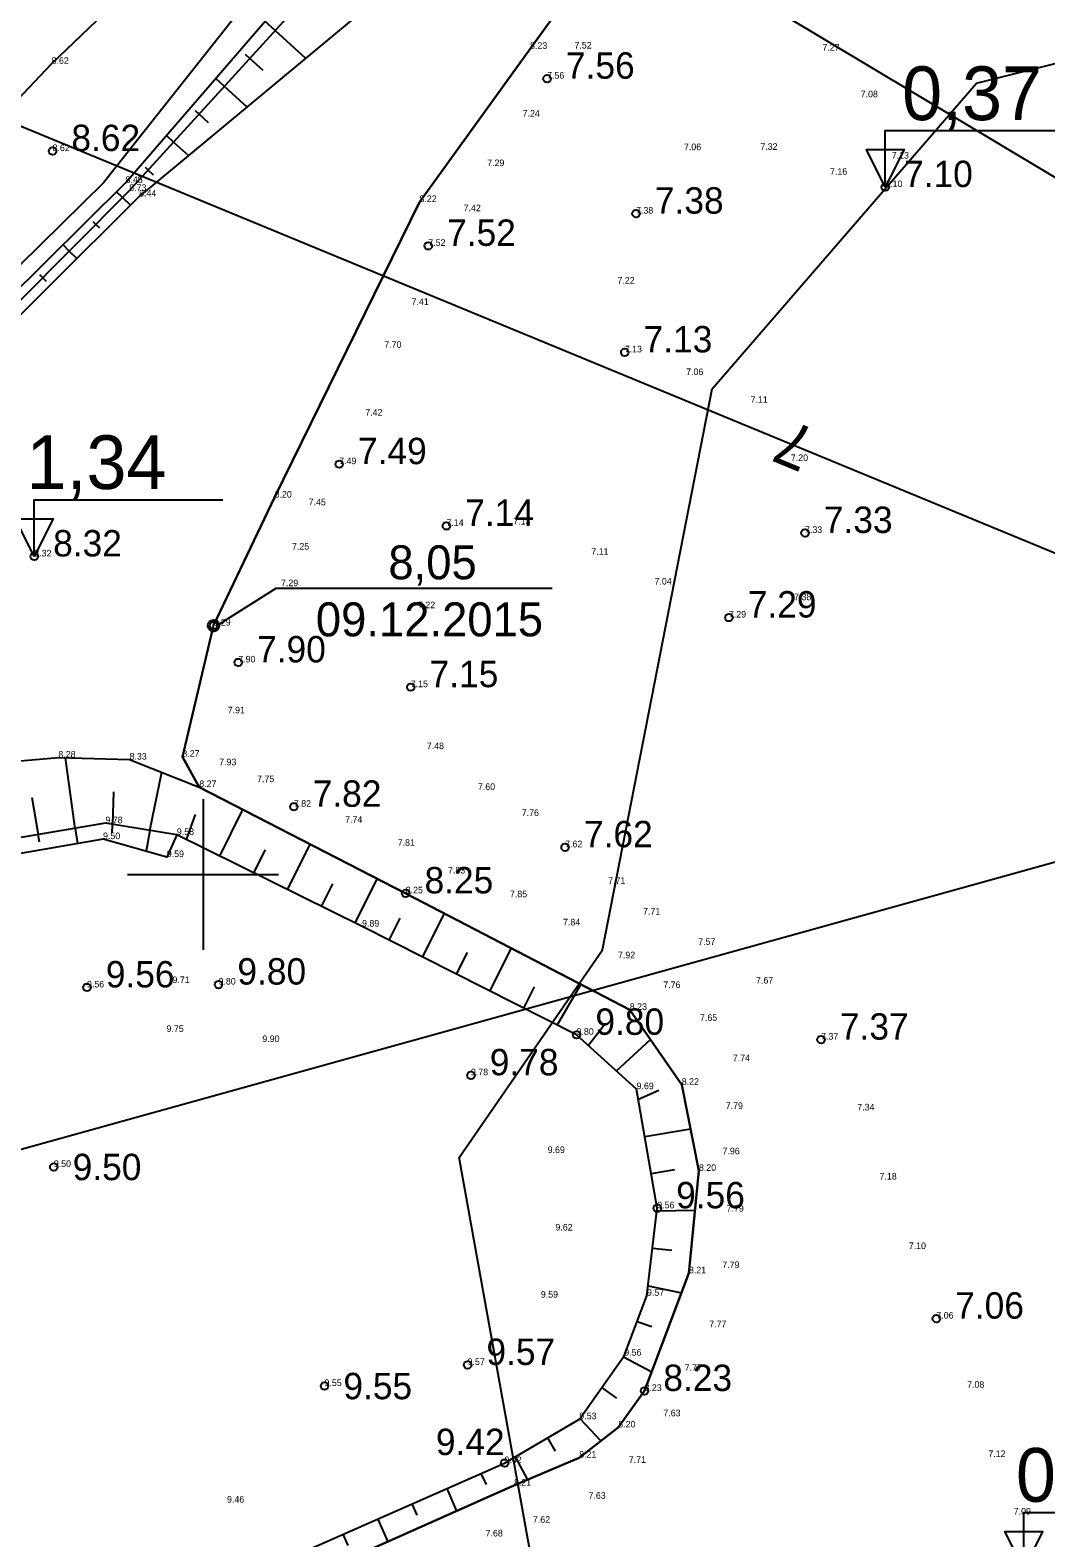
# Model space of a CAD drawing. Extents: x 433497 to 434382, y 6534486 to 6534993.
# Drawn here: x 433890.8 to 433944.7, y 6534764.8 to 6534844.8 of the extents above; entities that cross this region are included whole.
import ezdxf

# ---------------------------------------------------------------- set-up
doc = ezdxf.new("R2010")
doc.units = 0
for name, color, linetype in [('jääkpaksus', 7, 'Continuous'), ('KORGUS', 7, 'Continuous'), ('KORGUS-EH2000', 7, 'Continuous'), ('l__x00e4__bil__x00f5__iked', 7, 'Continuous'), ('Lamami horisontaal', 7, 'Continuous'), ('MOOTKORG-EH2000', 7, 'Continuous'), ('PIIR', 7, 'Continuous'), ('RELJEEF', 7, 'Continuous'), ('TEE', 7, 'Continuous'), ('VEEKOGU', 7, 'Continuous'), ('VORK', 7, 'Continuous')]:
    doc.layers.add(name, color=color, linetype=linetype)

msp = doc.modelspace()

# ---------------------------------------------------------------- linework, layer by layer
at = {"layer": 'jääkpaksus'}
for points in [[(433936.167, 6534836.451), (433936.167, 6534839.451), (433946.167, 6534839.451)], [(433891.052, 6534816.863), (433891.052, 6534819.863), (433901.052, 6534819.863)], [(433943.508, 6534763.157), (433943.508, 6534766.157), (433953.508, 6534766.157)]]:
    msp.add_lwpolyline(points, dxfattribs=at)
for points in [[(433936.167, 6534836.451), (433935.167, 6534838.451), (433937.167, 6534838.451)], [(433891.052, 6534816.863), (433890.052, 6534818.863), (433892.052, 6534818.863)], [(433943.508, 6534763.157), (433942.508, 6534765.157), (433944.508, 6534765.157)]]:
    msp.add_lwpolyline(points, close=True, dxfattribs=at)
at = {"layer": 'KORGUS'}
for centre in [(433892.086, 6534784.487), (433906.439, 6534772.869)]:
    msp.add_circle(centre, 0.2, dxfattribs=at)
at = {"layer": 'KORGUS-EH2000'}
for centre in [(433918.239, 6534842.2), (433892.019, 6534838.361), (433936.167, 6534836.451), (433922.956, 6534835.043), (433911.94, 6534833.335), (433922.358, 6534827.686), (433907.215, 6534821.758), (433912.903, 6534818.485), (433931.914, 6534818.11), (433891.052, 6534816.863), (433927.88, 6534813.625), (433901.866, 6534811.243), (433911.012, 6534809.931), (433904.812, 6534803.588), (433919.195, 6534801.44), (433910.743, 6534798.994), (433893.844, 6534794.007), (433900.819, 6534794.16), (433919.801, 6534791.494), (433932.765, 6534791.239), (433914.2, 6534789.346), (433892.086, 6534784.487), (433924.081, 6534782.294), (433938.877, 6534776.443), (433914.023, 6534773.986), (433923.404, 6534772.606), (433915.987, 6534768.78)]:
    msp.add_circle(centre, 0.2, dxfattribs=at)
at = {"layer": 'l__x00e4__bil__x00f5__iked'}
for points in [[(433837.129, 6534901.88), (433863.279, 6534885.992), (433986.579, 6534812.177), (434090.185, 6534779.904), (434120.969, 6534768.153)], [(433620.07, 6534691.039), (433627.105, 6534692.187), (433736.834, 6534712.709), (433742.792, 6534710.723), (433822.234, 6534766.498), (433986.579, 6534812.177), (434120.472, 6534848.091), (434132.163, 6534850.175)]]:
    msp.add_lwpolyline(points, dxfattribs=at)
at = {"layer": 'Lamami horisontaal'}
msp.add_lwpolyline([(433937.053, 6534740.112), (433960.879, 6534790.248), (433963.322, 6534798.12), (433962.586, 6534804.768), (433958.672, 6534810.191), (433951.578, 6534814.39), (433862.504, 6534851.176), (433857.642, 6534852.614), (433852.859, 6534852.881), (433848.155, 6534851.977), (433843.529, 6534849.902), (433823.019, 6534838.004), (433819.889, 6534836.728), (433817.507, 6534836.964), (433815.874, 6534838.714), (433814.99, 6534841.977), (433812.452, 6534861.972), (433812.459, 6534863.884), (433813.004, 6534865.497), (433813.579, 6534866.195)], dxfattribs=at)
at = {"layer": 'PIIR'}
msp.add_lwpolyline([(433924.608, 6534718.343), (433917.99, 6534737.895), (433917.54, 6534763.005), (433913.58, 6534784.995), (433921.17, 6534796.005), (433926.99, 6534825.75), (433941, 6534841.965), (433961.01, 6534846.975), (433983.99, 6534835.44), (434035.235, 6534886.132)], dxfattribs=at)
at = {"layer": 'RELJEEF'}
for p, q in [((433903.823, 6534844.753), (433903.282, 6534845.245)), ((433903.823, 6534844.753), (433905.431, 6534843.29)), ((433902.227, 6534843.501), (433902.478, 6534843.273)), ((433903.178, 6534842.636), (433902.478, 6534843.273)), ((433901.132, 6534841.794), (433900.669, 6534842.215)), ((433901.132, 6534841.794), (433902.325, 6534840.708)), ((433899.574, 6534840.507), (433899.786, 6534840.314)), ((433900.279, 6534839.865), (433899.786, 6534840.314)), ((433898.44, 6534838.835), (433898.055, 6534839.185)), ((433898.44, 6534838.835), (433899.22, 6534838.125)), ((433896.922, 6534837.514), (433897.094, 6534837.355)), ((433897.379, 6534837.093), (433897.094, 6534837.355)), ((433895.732, 6534835.892), (433895.412, 6534836.2)), ((433895.732, 6534835.892), (433896.145, 6534835.493)), ((433894.158, 6534834.636), (433894.321, 6534834.475)), ((433894.521, 6534834.275), (433894.321, 6534834.475)), ((433892.909, 6534833.058), (433892.575, 6534833.39)), ((433892.909, 6534833.058), (433893.304, 6534832.664)), ((433891.326, 6534831.812), (433891.498, 6534831.641)), ((433891.692, 6534831.447), (433891.498, 6534831.641)), ((433893.226, 6534802.444), (433892.711, 6534806.189)), ((433897.172, 6534802.33), (433897.805, 6534805.42)), ((433890.92, 6534804.08), (433891.254, 6534802.11)), ((433895.247, 6534804.383), (433895.198, 6534802.652)), ((433899.58, 6534803.175), (433899.096, 6534801.854)), ((433900.889, 6534800.966), (433902.114, 6534803.441)), ((433893.226, 6534802.444), (433893.337, 6534801.637)), ((433895.185, 6534802.196), (433895.198, 6534802.652)), ((433897.172, 6534802.33), (433896.991, 6534801.226)), ((433891.322, 6534801.705), (433891.254, 6534802.11)), ((433904.473, 6534799.191), (433905.67, 6534801.608)), ((433903.286, 6534801.302), (433902.681, 6534800.079)), ((433908.058, 6534797.416), (433909.233, 6534799.772)), ((433906.857, 6534799.498), (433906.265, 6534798.304)), ((433910.432, 6534797.684), (433909.845, 6534796.518)), ((433911.63, 6534795.617), (433912.796, 6534797.927)), ((433913.993, 6534795.86), (433913.416, 6534794.716)), ((433915.201, 6534793.815), (433916.345, 6534796.082)), ((433918.772, 6534792.013), (433920.021, 6534794.172)), ((433917.553, 6534794.037), (433916.987, 6534792.914)), ((433921.267, 6534792.007), (433920.43, 6534790.925)), ((433921.912, 6534789.583), (433923.714, 6534791.246)), ((433924.167, 6534788.544), (433923.079, 6534788.066)), ((433923.421, 6534786.096), (433925.843, 6534786.516)), ((433925.002, 6534784.327), (433923.763, 6534784.125)), ((433924.064, 6534782.153), (433926.086, 6534782.189)), ((433924.849, 6534780.048), (433923.831, 6534780.167)), ((433923.598, 6534778.181), (433925.369, 6534777.808)), ((433923.799, 6534776.007), (433923.013, 6534776.28)), ((433922.287, 6534774.419), (433923.785, 6534773.614)), ((433921.929, 6534772.224), (433921.133, 6534772.786)), ((433919.979, 6534771.152), (433921.09, 6534769.958)), ((433918.689, 6534769.417), (433918.27, 6534770.122)), ((433916.546, 6534769.109), (433917.198, 6534767.892)), ((433915.023, 6534767.646), (433914.75, 6534768.235)), ((433912.92, 6534767.428), (433913.445, 6534766.237)), ((433911.354, 6534766.023), (433911.09, 6534766.621)), ((433909.26, 6534765.814), (433909.789, 6534764.614)), ((433907.695, 6534764.405), (433907.43, 6534765.008))]:
    msp.add_line(p, q, dxfattribs=at)
for points in [[(433898.612, 6534802.094), (433898.076, 6534800.92), (433894.697, 6534801.873), (433884.69, 6534800.138), (433872.871, 6534792.485), (433865.209, 6534789.352), (433856.709, 6534790.266), (433854.429, 6534791.927), (433850.926, 6534796.169), (433848.567, 6534800.946), (433849.25, 6534803.887), (433849.579, 6534804.828), (433855.051, 6534806.361), (433863.497, 6534809.37), (433872.433, 6534814.392), (433881.08, 6534822.005), (433895.887, 6534836.671), (433906.99, 6534849.543)], [(433881.396, 6534821.499), (433896.085, 6534836.246), (433907.73, 6534849.047)], [(433909.717, 6534846.854), (433896.607, 6534835.953), (433881.875, 6534821.287)], [(433883.794, 6534805.462), (433892.328, 6534806.2), (433896.102, 6534806.091), (433899.798, 6534804.634), (433910.743, 6534798.994), (433922.624, 6534792.819), (433925.378, 6534788.845), (433926.29, 6534784.28), (433925.761, 6534778.847), (433923.404, 6534772.606), (433922.013, 6534770.671), (433919.938, 6534769.068), (433916.484, 6534767.586), (433905.134, 6534762.547)], [(433904.949, 6534763.914), (433915.987, 6534768.78), (433919.949, 6534771.11), (433922.329, 6534774.479), (433923.536, 6534777.656), (433924.081, 6534782.294), (433922.984, 6534788.612), (433919.801, 6534791.494), (433908.429, 6534797.232), (433898.612, 6534802.094), (433894.822, 6534802.714), (433884.378, 6534800.945)]]:
    msp.add_lwpolyline(points, dxfattribs=at)
at = {"layer": 'TEE'}
for points in [[(433861.438, 6534942.159), (433869.211, 6534941.983), (433884.56, 6534941.789), (433912.385, 6534941.438), (433914.504, 6534939.939), (433923.131, 6534931.509), (433926.468, 6534922.294), (433926.566, 6534912.494), (433924.107, 6534897.344), (433917.239, 6534875.453), (433907.496, 6534860.59), (433898.243, 6534848.994), (433898.296, 6534849.051), (433891.969, 6534842.99)], [(433946.971, 6534921.598), (433938.961, 6534918.789), (433932.862, 6534915.346), (433929.862, 6534910.084), (433927.993, 6534899.902), (433926.253, 6534890.427), (433921.703, 6534874.038), (433912.286, 6534858.358), (433907.932, 6534852.587), (433902.598, 6534846.653), (433894.713, 6534836.682), (433880.242, 6534822.442), (433871.952, 6534814.761), (433862.656, 6534809.713), (433848.041, 6534804.286)], [(433891.969, 6534842.99), (433881.334, 6534831.763), (433873.157, 6534823.586), (433858.917, 6534813.356), (433845.699, 6534809.155)]]:
    msp.add_lwpolyline(points, dxfattribs=at)
at = {"layer": 'VEEKOGU'}
for points in [[(433905.134, 6534762.547), (433916.484, 6534767.586), (433919.938, 6534769.068), (433922.013, 6534770.671), (433923.404, 6534772.606), (433925.761, 6534778.847), (433926.29, 6534784.28), (433925.378, 6534788.845), (433922.624, 6534792.819), (433910.743, 6534798.994), (433899.798, 6534804.634), (433898.901, 6534806.241), (433900.552, 6534813.199), (433903.795, 6534819.986), (433911.474, 6534835.66), (433917.335, 6534843.781), (433923.831, 6534852.766), (433925.728, 6534858.785), (433925.594, 6534862.047), (433930.79, 6534874.949), (433935.088, 6534889.742), (433939.821, 6534890.613), (433944.672, 6534889.281), (433947.125, 6534887.427)], [(433950.327, 6534886.209), (433947.125, 6534887.427), (433944.672, 6534889.281), (433939.821, 6534890.613), (433935.088, 6534889.742), (433930.79, 6534874.949), (433925.594, 6534862.047), (433925.728, 6534858.785), (433923.831, 6534852.766), (433917.335, 6534843.781), (433911.474, 6534835.66), (433903.795, 6534819.986), (433900.681, 6534813.47)], [(433918.513, 6534815.161), (433903.866, 6534815.161), (433900.752, 6534813.199)], [(433900.483, 6534812.907), (433898.901, 6534806.241), (433899.798, 6534804.634), (433910.743, 6534798.994), (433922.624, 6534792.819), (433925.378, 6534788.845), (433926.29, 6534784.28), (433925.761, 6534778.847), (433923.404, 6534772.606), (433922.013, 6534770.671), (433919.938, 6534769.068), (433916.484, 6534767.586), (433905.134, 6534762.547)]]:
    msp.add_lwpolyline(points, dxfattribs=at)
for radius in [0.3, 0.2]:
    msp.add_circle((433900.552, 6534813.199), radius, dxfattribs=at)
msp.add_arc((433900.552, 6534813.199), 0.3, 256.65167, 64.46035, dxfattribs=at)
at = {"layer": 'VORK'}
for p, q in [((433900, 6534804), (433900, 6534796)), ((433896, 6534800), (433904, 6534800))]:
    msp.add_line(p, q, dxfattribs=at)

# ---------------------------------------------------------------- texts
at = {"layer": 'jääkpaksus'}
for s, p in [('0,37', (433937.063, 6534840.002)), ('1,34', (433890.64, 6534820.438)), ('0,52', (433943.096, 6534766.732))]:
    msp.add_text(s, height=2.85, rotation=360, dxfattribs=at).set_placement(p)
at = {"layer": 'KORGUS-EH2000'}
for s, p in [('7.56', (433919.239, 6534842.2)), ('8.62', (433893.019, 6534838.361)), ('7.10', (433937.167, 6534836.451)), ('7.38', (433923.956, 6534835.043)), ('7.52', (433912.94, 6534833.335)), ('7.13', (433923.358, 6534827.686)), ('7.49', (433908.215, 6534821.758)), ('7.14', (433913.903, 6534818.485)), ('7.33', (433932.914, 6534818.11)), ('8.32', (433892.052, 6534816.863)), ('7.29', (433928.88, 6534813.625)), ('7.90', (433902.866, 6534811.243)), ('7.15', (433912.012, 6534809.931)), ('7.82', (433905.812, 6534803.588)), ('7.62', (433920.195, 6534801.44)), ('8.25', (433911.743, 6534798.994)), ('9.56', (433894.844, 6534794.007)), ('9.80', (433901.819, 6534794.16)), ('9.80', (433920.801, 6534791.494)), ('7.37', (433933.765, 6534791.239)), ('9.78', (433915.2, 6534789.346)), ('9.50', (433893.086, 6534783.787)), ('9.56', (433925.081, 6534782.294)), ('7.06', (433939.877, 6534776.443)), ('9.57', (433915.023, 6534773.986)), ('9.55', (433907.439, 6534772.169)), ('8.23', (433924.404, 6534772.606)), ('9.42', (433912.345, 6534769.207))]:
    msp.add_text(s, height=1.4, dxfattribs=at).set_placement(p)
at = {"layer": 'Lamami horisontaal'}
msp.add_text('7', height=2.4, rotation=157.56033, dxfattribs=at).set_placement((433932.62, 6534823.517))
at = {"layer": 'MOOTKORG-EH2000'}
for s, p in [('8.23', (433917.335, 6534843.781)), ('7.52', (433919.689, 6534843.8)), ('7.27', (433932.837, 6534843.689)), ('8.62', (433891.969, 6534842.99)), ('7.56', (433918.239, 6534842.2)), ('7.08', (433934.867, 6534841.214)), ('7.24', (433916.943, 6534840.186)), ('8.62', (433892.019, 6534838.361)), ('7.06', (433925.497, 6534838.41)), ('7.32', (433929.547, 6534838.427)), ('7.13', (433936.512, 6534837.959)), ('7.29', (433915.064, 6534837.563)), ('7.16', (433933.239, 6534837.103)), ('8.45', (433895.887, 6534836.671)), ('8.73', (433896.085, 6534836.246)), ('7.10', (433936.167, 6534836.451)), ('8.44', (433896.607, 6534835.953)), ('8.22', (433911.474, 6534835.66)), ('7.42', (433913.815, 6534835.174)), ('7.38', (433922.956, 6534835.043)), ('7.52', (433911.94, 6534833.335)), ('7.22', (433921.97, 6534831.332)), ('7.41', (433911.055, 6534830.202)), ('7.70', (433909.607, 6534827.93)), ('7.13', (433922.358, 6534827.686)), ('7.06', (433925.612, 6534826.483)), ('7.11', (433929.032, 6534825.012)), ('7.42', (433908.602, 6534824.328)), ('7.20', (433931.165, 6534821.923)), ('7.49', (433907.215, 6534821.758)), ('8.20', (433903.795, 6534819.986)), ('7.45', (433905.597, 6534819.575)), ('7.14', (433912.903, 6534818.485)), ('7.13', (433916.446, 6534818.556)), ('7.33', (433931.914, 6534818.11)), ('7.25', (433904.715, 6534817.225)), ('8.32', (433891.052, 6534816.863)), ('7.11', (433920.584, 6534816.953)), ('7.29', (433904.133, 6534815.288)), ('7.04', (433923.938, 6534815.374)), ('7.22', (433911.395, 6534814.119)), ('7.38', (433931.338, 6534814.544)), ('8.29', (433900.552, 6534813.199)), ('7.29', (433927.88, 6534813.625)), ('7.90', (433901.866, 6534811.243)), ('7.15', (433911.012, 6534809.931)), ('7.91', (433901.307, 6534808.541)), ('7.48', (433911.861, 6534806.644)), ('8.28', (433892.328, 6534806.2)), ('8.33', (433896.102, 6534806.091)), ('8.27', (433898.901, 6534806.241)), ('7.93', (433900.851, 6534805.788)), ('8.27', (433899.798, 6534804.634)), ('7.75', (433902.864, 6534804.893)), ('7.60', (433914.572, 6534804.48)), ('7.82', (433904.812, 6534803.588)), ('9.78', (433894.822, 6534802.714)), ('7.74', (433907.532, 6534802.738)), ('7.76', (433916.895, 6534803.099)), ('9.50', (433894.697, 6534801.873)), ('9.58', (433898.612, 6534802.094)), ('7.81', (433910.32, 6534801.519)), ('7.62', (433919.195, 6534801.44)), ('9.59', (433898.076, 6534800.92)), ('7.83', (433912.987, 6534800.05)), ('7.71', (433921.475, 6534799.495)), ('8.25', (433910.743, 6534798.994)), ('7.85', (433916.271, 6534798.792)), ('7.71', (433923.327, 6534797.872)), ('9.89', (433908.429, 6534797.232)), ('7.84', (433919.085, 6534797.296)), ('7.57', (433926.25, 6534796.265)), ('7.92', (433921.999, 6534795.553)), ('9.56', (433893.844, 6534794.007)), ('9.71', (433898.378, 6534794.238)), ('9.80', (433900.819, 6534794.16)), ('7.76', (433924.401, 6534793.975)), ('7.67', (433929.317, 6534794.214)), ('8.23', (433922.624, 6534792.819)), ('7.65', (433926.347, 6534792.234)), ('9.75', (433898.063, 6534791.649)), ('9.80', (433919.801, 6534791.494)), ('9.90', (433903.143, 6534791.11)), ('7.37', (433932.765, 6534791.239)), ('7.74', (433928.087, 6534790.095)), ('9.78', (433914.2, 6534789.346)), ('9.69', (433922.984, 6534788.612)), ('8.22', (433925.378, 6534788.845)), ('7.79', (433927.711, 6534787.563)), ('7.34', (433934.685, 6534787.484)), ('9.69', (433918.269, 6534785.227)), ('7.96', (433927.54, 6534785.157)), ('9.50', (433892.086, 6534784.487)), ('8.20', (433926.29, 6534784.28)), ('7.18', (433935.865, 6534783.821)), ('9.56', (433924.081, 6534782.294)), ('7.79', (433927.755, 6534782.114)), ('9.62', (433918.682, 6534781.117)), ('7.10', (433937.416, 6534780.132)), ('8.21', (433925.761, 6534778.847)), ('7.79', (433927.528, 6534779.123)), ('9.59', (433917.908, 6534777.554)), ('9.57', (433923.536, 6534777.656)), ('7.06', (433938.877, 6534776.443)), ('7.77', (433926.836, 6534775.984)), ('9.57', (433914.023, 6534773.986)), ('9.56', (433922.329, 6534774.479)), ('7.77', (433925.534, 6534773.678)), ('9.55', (433906.439, 6534772.869)), ('8.23', (433923.404, 6534772.606)), ('7.08', (433940.508, 6534772.776)), ('9.53', (433919.949, 6534771.11)), ('8.20', (433922.013, 6534770.671)), ('7.63', (433924.403, 6534771.264)), ('8.21', (433919.938, 6534769.068)), ('7.12', (433941.636, 6534769.101)), ('9.42', (433915.987, 6534768.78)), ('7.71', (433922.57, 6534768.794)), ('8.21', (433916.484, 6534767.586)), ('9.46', (433901.27, 6534766.682)), ('7.63', (433920.436, 6534766.89)), ('7.09', (433942.979, 6534766.054)), ('7.62', (433917.487, 6534765.617)), ('7.68', (433914.979, 6534764.891))]:
    msp.add_text(s, height=0.35, dxfattribs=at).set_placement(p)
at = {"layer": 'VEEKOGU'}
for s, p in [('8,05', (433909.824, 6534815.653)), ('09.12.2015', (433905.98, 6534812.628))]:
    msp.add_text(s, height=1.8, dxfattribs=at).set_placement(p)

doc.saveas('drawing.dxf')
